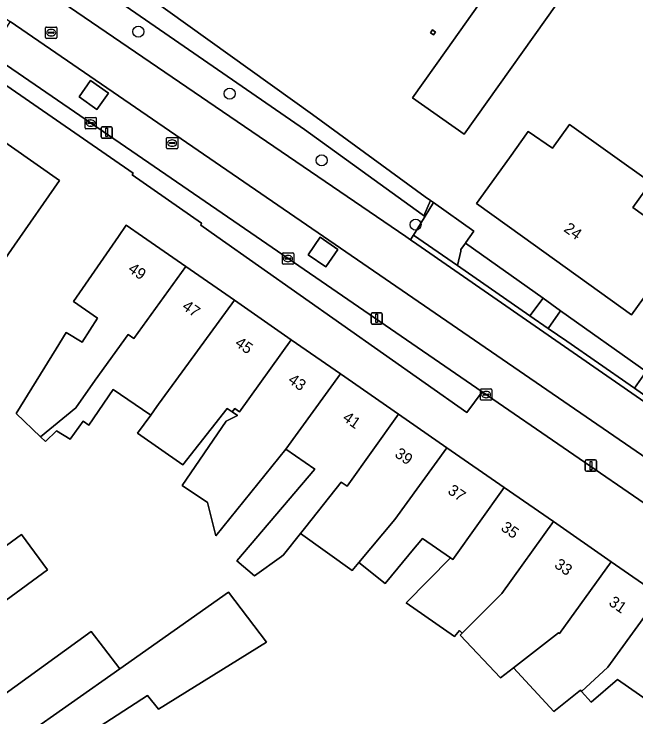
# Model space of a CAD drawing. Extents: x 163859 to 164644, y 379566 to 382155.
# Drawn here: x 164325.1 to 164380.2, y 381707.4 to 381769.7 of the extents above; entities that cross this region are included whole.
import ezdxf

# ---------------------------------------------------------------- set-up
doc = ezdxf.new("R2010")
doc.units = 0
for name, color, linetype in [('IMGEO_Boom', 7, 'Continuous'), ('IMGEO_Brandkraan', 7, 'Continuous'), ('IMGEO_Erf', 7, 'Continuous'), ('IMGEO_Groenvoorziening', 7, 'Continuous'), ('IMGEO_Haag', 7, 'Continuous'), ('IMGEO_Kolk', 7, 'Continuous'), ('IMGEO_Lichtmast', 7, 'Continuous'), ('IMGEO_Pand', 7, 'Continuous'), ('IMGEO_Pand_nummerreeks', 7, 'Continuous'), ('IMGEO_Parkeervlak_open', 7, 'Continuous'), ('IMGEO_Rijbaan_lokaal_gesloten', 7, 'Continuous'), ('IMGEO_Rijbaan_lokaal_open', 7, 'Continuous'), ('IMGEO_Rioolput', 7, 'Continuous'), ('IMGEO_Voetpad_halfverhard', 7, 'Continuous'), ('IMGEO_Voetpad_open', 7, 'Continuous'), ('IMGEO_Waterloop', 7, 'Continuous')]:
    doc.layers.add(name, color=color, linetype=linetype)

msp = doc.modelspace()

# ---------------------------------------------------------------- linework, layer by layer
at = {"layer": 'IMGEO_Boom'}
for centre in [(164336.114, 381768.169), (164344.218, 381762.677), (164352.371, 381756.76), (164360.689, 381751.063)]:
    msp.add_circle(centre, 0.489, dxfattribs=at)
at = {"layer": 'IMGEO_Brandkraan'}
for p, q in [((164338.611, 381757.863), (164338.611, 381758.715)), ((164338.686, 381758.789), (164339.538, 381758.789)), ((164339.099, 381758.569), (164339.124, 381758.569)), ((164339.612, 381758.715), (164339.612, 381757.863)), ((164338.87, 381758.283), (164338.87, 381758.295)), ((164339.308, 381758.246), (164338.91, 381758.246)), ((164338.913, 381758.332), (164339.311, 381758.332)), ((164339.122, 381758.009), (164339.097, 381758.009)), ((164339.354, 381758.295), (164339.354, 381758.283)), ((164339.538, 381757.789), (164338.686, 381757.789))]:
    msp.add_line(p, q, dxfattribs=at)
for points in [[(164338.611, 381757.863), (164338.611, 381758.715)], [(164338.686, 381758.789), (164339.538, 381758.789)], [(164339.612, 381758.715), (164339.612, 381757.863)], [(164339.538, 381757.789), (164338.686, 381757.789)]]:
    msp.add_lwpolyline(points, dxfattribs=at)
for centre, radius, start, end in [((164338.688, 381758.713), 0.0765, 91.55205, 178.44795), ((164338.688, 381758.713), 0.0765, 91.55205, 178.44795), ((164339.536, 381758.713), 0.0765, 1.55205, 88.44795), ((164339.536, 381758.713), 0.0765, 1.55205, 88.44795), ((164338.688, 381757.865), 0.0765, 181.55205, 268.44795), ((164338.688, 381757.865), 0.0765, 181.55205, 268.44795), ((164338.91, 381758.292), 0.0403, 85.87752, 175.75265), ((164338.907, 381758.282), 0.0366, 178.93798, 274.71019), ((164339.311, 381758.289), 0.043, 264.86636, 352.45326), ((164339.315, 381758.294), 0.0386, 1.73085, 96.63898), ((164339.536, 381757.865), 0.0765, 271.55205, 358.44795), ((164339.536, 381757.865), 0.0765, 271.55205, 358.44795)]:
    msp.add_arc(centre, radius, start, end, dxfattribs=at)
for centre, major_axis, ratio, start_param, end_param in [((164339.098, 381758.289), (-0.387, 0.002), 0.722429, 4.712389, 7.853982), ((164339.123, 381758.289), (-0.39, 0.002), 0.717154, 1.570796, 4.712389)]:
    msp.add_ellipse(centre, major_axis=major_axis, ratio=ratio, start_param=start_param, end_param=end_param, dxfattribs=at)
at = {"layer": 'IMGEO_Erf'}
for points in [[(164392.726, 381806.597), (164338.747, 381777.229), (164335.006, 381775.051), (164333.203, 381774.002), (164351.545, 381760.837), (164361.552, 381753.543), (164362.019, 381753.203), (164362.264, 381753.03), (164365.86, 381750.491), (164365.15, 381749.485), (164365.11, 381749.429), (164371.983, 381744.544), (164373.541, 381743.437), (164381.128, 381738.044), (164380.075, 381736.577), (164381.302, 381735.727)], [(164381.892, 381725.724), (164366.579, 381736.251), (164365.238, 381734.407), (164343.09, 381750), (164341.646, 381751.017), (164341.728, 381751.199), (164335.582, 381755.465), (164335.669, 381755.626), (164322.057, 381765.024), (164322.896, 381766.247), (164322.167, 381766.721), (164321.202, 381765.27), (164309.218, 381773.471), (164309.769, 381774.13), (164309.527, 381774.292), (164308.748, 381773.279), (164308.401, 381772.828), (164307.015, 381771.024), (164290.861, 381750), (164280.775, 381736.889), (164280.475, 381736.472), (164297.431, 381715.017), (164336.625, 381665.424)], [(164382.491, 381708.022), (164378.587, 381710.736), (164376.254, 381708.729), (164375.391, 381709.7), (164375.31, 381709.792), (164372.95, 381707.902), (164369.371, 381711.799), (164368.221, 381710.906), (164364.655, 381714.683), (164364.832, 381714.86), (164364.572, 381715.105), (164364.139, 381714.554), (164359.852, 381717.545), (164363.776, 381721.527), (164361.292, 381723.25), (164360.83, 381722.692), (164360.648, 381722.472), (164357.992, 381719.262), (164355.658, 381721.111), (164355.072, 381720.411), (164350.492, 381723.687), (164348.988, 381721.786), (164348.799, 381721.652), (164346.4, 381719.939), (164344.855, 381721.269), (164351.754, 381729.39), (164349.184, 381731.176), (164342.992, 381723.477), (164342.241, 381726.45), (164339.999, 381727.945), (164343.893, 381733.653), (164344.898, 381734.156), (164344.447, 381734.469), (164344.003, 381734.777), (164340.064, 381729.783), (164336.057, 381732.584), (164337.215, 381734.183), (164337.128, 381734.243), (164333.902, 381736.447), (164331.739, 381733.298), (164331.228, 381733.653), (164330.087, 381732.039), (164328.868, 381732.787), (164327.884, 381731.842), (164327.448, 381732.259), (164325.288, 381734.322), (164328.828, 381740.068), (164329.722, 381741.519), (164331.136, 381740.648), (164332.504, 381742.772), (164330.372, 381744.254), (164332.233, 381746.93), (164334.357, 381750), (164335.053, 381751.006), (164336.503, 381750), (164340.315, 381747.355), (164344.634, 381744.357), (164349.676, 381740.859), (164354.042, 381737.829), (164359.164, 381734.275), (164363.467, 381731.289), (164368.546, 381727.764), (164372.899, 381724.743), (164378.015, 381721.193), (164382.346, 381718.188)], [(164324.281, 381704.515), (164321.939, 381707.778), (164331.952, 381715.004), (164333.032, 381713.589), (164334.47, 381711.704), (164344.097, 381718.497), (164347.475, 381714.073), (164337.908, 381708.113), (164336.94, 381709.343), (164326.849, 381702.817)]]:
    msp.add_lwpolyline(points, dxfattribs=at)
for points in [[(164364.99, 381759.075), (164360.427, 381762.301), (164363.402, 381766.508), (164369.661, 381775.357), (164374.23, 381772.12)], [(164362.279, 381767.877), (164362.018, 381768.062), (164362.203, 381768.324), (164362.464, 381768.139)], [(164320.981, 381743.295), (164317.322, 381745.846), (164321.205, 381751.416), (164318.285, 381753.452), (164317.93, 381752.943), (164313.509, 381756.026), (164316.591, 381760.447), (164320.99, 381757.29), (164322.574, 381759.563), (164329.133, 381754.99), (164325.139, 381749.259), (164322.268, 381745.141)], [(164384.356, 381749.398), (164386.461, 381747.871), (164383.511, 381743.759), (164381.407, 381745.286), (164379.821, 381743.076), (164370.167, 381750), (164366.083, 381752.929), (164368.998, 381756.992), (164370.67, 381759.324), (164372.81, 381757.83), (164374.323, 381759.95), (164381.542, 381754.8), (164379.945, 381752.598), (164383.526, 381750)], [(164324.402, 381717.768), (164322.084, 381720.911), (164325.769, 381723.593), (164328.077, 381720.464)]]:
    msp.add_lwpolyline(points, close=True, dxfattribs=at)
at = {"layer": 'IMGEO_Groenvoorziening'}
msp.add_lwpolyline([(164324.169, 381774.363), (164359.822, 381750), (164360.25, 381749.708), (164360.489, 381750.103), (164360.511, 381750.139), (164361.118, 381751.14), (164362.264, 381753.03), (164362.019, 381753.203), (164361.428, 381751.86), (164361.269, 381751.975), (164350.837, 381759.485), (164291.421, 381800.511), (164261.825, 381821.183)], dxfattribs=at)
for points in [[(164333.471, 381762.711), (164331.878, 381763.829), (164330.863, 381762.383), (164332.456, 381761.265)], [(164352.745, 381747.339), (164353.81, 381748.857), (164352.232, 381749.958), (164351.164, 381748.396)], [(164365.11, 381749.429), (164364.703, 381748.852), (164364.689, 381748.711), (164364.415, 381747.432), (164370.817, 381742.995), (164370.827, 381742.988), (164371.983, 381744.544)], [(164373.541, 381743.437), (164372.441, 381741.869), (164374.088, 381740.727), (164379.696, 381736.84), (164380.075, 381736.577), (164381.128, 381738.044)]]:
    msp.add_lwpolyline(points, close=True, dxfattribs=at)
at = {"layer": 'IMGEO_Haag'}
msp.add_lwpolyline([(164352.745, 381747.339), (164353.81, 381748.857), (164352.232, 381749.958), (164351.164, 381748.396)], close=True, dxfattribs=at)
at = {"layer": 'IMGEO_Kolk'}
for p, q in [((164331.397, 381759.642), (164331.397, 381760.494)), ((164331.472, 381760.568), (164332.324, 381760.568)), ((164331.885, 381760.348), (164331.91, 381760.348)), ((164332.398, 381760.494), (164332.398, 381759.642)), ((164331.656, 381760.062), (164331.656, 381760.074)), ((164332.094, 381760.025), (164331.696, 381760.025)), ((164331.699, 381760.111), (164332.097, 381760.111)), ((164331.908, 381759.788), (164331.883, 381759.788)), ((164332.14, 381760.074), (164332.14, 381760.062)), ((164332.324, 381759.568), (164331.472, 381759.568)), ((164348.961, 381748.558), (164349.813, 381748.558)), ((164348.886, 381747.632), (164348.886, 381748.484)), ((164349.145, 381748.052), (164349.145, 381748.064)), ((164349.583, 381748.015), (164349.185, 381748.015)), ((164349.188, 381748.101), (164349.586, 381748.101)), ((164349.374, 381748.338), (164349.399, 381748.338)), ((164349.629, 381748.064), (164349.629, 381748.052)), ((164349.887, 381748.484), (164349.887, 381747.632)), ((164349.813, 381747.558), (164348.961, 381747.558)), ((164349.397, 381747.778), (164349.372, 381747.778)), ((164366.438, 381735.579), (164366.438, 381736.431)), ((164366.513, 381736.505), (164367.365, 381736.505)), ((164366.74, 381736.048), (164367.138, 381736.048)), ((164366.926, 381736.285), (164366.951, 381736.285)), ((164367.439, 381736.431), (164367.439, 381735.579)), ((164367.365, 381735.505), (164366.513, 381735.505)), ((164366.697, 381735.999), (164366.697, 381736.011)), ((164367.135, 381735.962), (164366.737, 381735.962)), ((164366.949, 381735.725), (164366.924, 381735.725)), ((164367.181, 381736.011), (164367.181, 381735.999))]:
    msp.add_line(p, q, dxfattribs=at)
for points in [[(164331.397, 381759.642), (164331.397, 381760.494)], [(164331.472, 381760.568), (164332.324, 381760.568)], [(164332.398, 381760.494), (164332.398, 381759.642)], [(164332.324, 381759.568), (164331.472, 381759.568)], [(164348.961, 381748.558), (164349.813, 381748.558)], [(164348.886, 381747.632), (164348.886, 381748.484)], [(164349.887, 381748.484), (164349.887, 381747.632)], [(164349.813, 381747.558), (164348.961, 381747.558)], [(164366.438, 381735.579), (164366.438, 381736.431)], [(164366.513, 381736.505), (164367.365, 381736.505)], [(164367.439, 381736.431), (164367.439, 381735.579)], [(164367.365, 381735.505), (164366.513, 381735.505)]]:
    msp.add_lwpolyline(points, dxfattribs=at)
for centre, radius, start, end in [((164331.474, 381760.492), 0.0765, 91.55205, 178.44795), ((164331.474, 381760.492), 0.0765, 91.55205, 178.44795), ((164332.322, 381760.492), 0.0765, 1.55205, 88.44795), ((164332.322, 381760.492), 0.0765, 1.55205, 88.44795), ((164331.696, 381760.071), 0.0403, 85.87752, 175.75265), ((164331.693, 381760.061), 0.0366, 178.93798, 274.71019), ((164332.097, 381760.068), 0.043, 264.86636, 352.45326), ((164332.101, 381760.073), 0.0386, 1.73085, 96.63898), ((164331.474, 381759.644), 0.0765, 181.55205, 268.44795), ((164331.474, 381759.644), 0.0765, 181.55205, 268.44795), ((164332.322, 381759.644), 0.0765, 271.55205, 358.44795), ((164332.322, 381759.644), 0.0765, 271.55205, 358.44795), ((164348.963, 381748.482), 0.0765, 91.55205, 178.44795), ((164348.963, 381748.482), 0.0765, 91.55205, 178.44795), ((164349.811, 381748.482), 0.0765, 1.55205, 88.44795), ((164349.811, 381748.482), 0.0765, 1.55205, 88.44795), ((164349.185, 381748.061), 0.0403, 85.87752, 175.75265), ((164349.182, 381748.051), 0.0366, 178.93798, 274.71019), ((164349.586, 381748.058), 0.043, 264.86636, 352.45326), ((164349.59, 381748.063), 0.0386, 1.73085, 96.63898), ((164348.963, 381747.634), 0.0765, 181.55205, 268.44795), ((164348.963, 381747.634), 0.0765, 181.55205, 268.44795), ((164349.811, 381747.634), 0.0765, 271.55205, 358.44795), ((164349.811, 381747.634), 0.0765, 271.55205, 358.44795), ((164366.515, 381736.429), 0.0765, 91.55205, 178.44795), ((164366.515, 381736.429), 0.0765, 91.55205, 178.44795), ((164366.737, 381736.008), 0.0403, 85.87752, 175.75265), ((164367.142, 381736.01), 0.0386, 1.73085, 96.63898), ((164367.363, 381736.429), 0.0765, 1.55205, 88.44795), ((164367.363, 381736.429), 0.0765, 1.55205, 88.44795), ((164366.515, 381735.581), 0.0765, 181.55205, 268.44795), ((164366.515, 381735.581), 0.0765, 181.55205, 268.44795), ((164366.734, 381735.998), 0.0366, 178.93798, 274.71019), ((164367.138, 381736.005), 0.043, 264.86636, 352.45326), ((164367.363, 381735.581), 0.0765, 271.55205, 358.44795), ((164367.363, 381735.581), 0.0765, 271.55205, 358.44795)]:
    msp.add_arc(centre, radius, start, end, dxfattribs=at)
for centre, major_axis, ratio, start_param, end_param in [((164331.884, 381760.068), (-0.387, 0.002), 0.722429, 4.712389, 7.853982), ((164331.909, 381760.068), (-0.39, 0.002), 0.717154, 1.570796, 4.712389), ((164349.373, 381748.058), (-0.387, 0.002), 0.722429, 4.712389, 7.853982), ((164349.398, 381748.058), (-0.39, 0.002), 0.717154, 1.570796, 4.712389), ((164366.925, 381736.005), (-0.387, 0.002), 0.722429, 4.712389, 7.853982), ((164366.95, 381736.005), (-0.39, 0.002), 0.717154, 1.570796, 4.712389)]:
    msp.add_ellipse(centre, major_axis=major_axis, ratio=ratio, start_param=start_param, end_param=end_param, dxfattribs=at)
at = {"layer": 'IMGEO_Lichtmast'}
for p, q in [((164332.917, 381759.742), (164333.707, 381759.742)), ((164333.707, 381759.742), (164332.917, 381759.742)), ((164332.817, 381758.842), (164332.817, 381759.642)), ((164332.817, 381759.642), (164332.817, 381758.842)), ((164333.807, 381759.642), (164333.807, 381758.842)), ((164333.807, 381758.842), (164333.807, 381759.642)), ((164333.707, 381758.742), (164332.917, 381758.742)), ((164332.917, 381758.742), (164333.707, 381758.742)), ((164356.751, 381742.357), (164356.751, 381743.157)), ((164356.751, 381743.157), (164356.751, 381742.357)), ((164356.851, 381743.257), (164357.641, 381743.257)), ((164357.641, 381743.257), (164356.851, 381743.257)), ((164357.741, 381743.157), (164357.741, 381742.357)), ((164357.741, 381742.357), (164357.741, 381743.157)), ((164357.641, 381742.257), (164356.851, 381742.257)), ((164356.851, 381742.257), (164357.641, 381742.257)), ((164375.726, 381729.309), (164375.726, 381730.109)), ((164375.726, 381730.109), (164375.726, 381729.309)), ((164375.826, 381730.209), (164376.616, 381730.209)), ((164376.616, 381730.209), (164375.826, 381730.209)), ((164376.716, 381730.109), (164376.716, 381729.309)), ((164376.716, 381729.309), (164376.716, 381730.109)), ((164376.616, 381729.209), (164375.826, 381729.209)), ((164375.826, 381729.209), (164376.616, 381729.209))]:
    msp.add_line(p, q, dxfattribs=at)
for points in [[(164333.237, 381759.617), (164333.387, 381759.617), (164333.387, 381758.867), (164333.237, 381758.867), (164333.237, 381759.617)], [(164357.171, 381743.132), (164357.321, 381743.132), (164357.321, 381742.382), (164357.171, 381742.382), (164357.171, 381743.132)], [(164376.146, 381730.084), (164376.296, 381730.084), (164376.296, 381729.334), (164376.146, 381729.334), (164376.146, 381730.084)]]:
    msp.add_lwpolyline(points, dxfattribs=at)
for centre, start, end in [((164332.917, 381759.642), 90, 180), ((164332.917, 381759.642), 90, 180), ((164333.707, 381759.642), 0, 90), ((164333.707, 381759.642), 360, 90), ((164332.917, 381758.842), 180, 270), ((164332.917, 381758.842), 180, 270), ((164333.707, 381758.842), 270, 0), ((164333.707, 381758.842), 270, 0), ((164356.851, 381743.157), 90, 180), ((164356.851, 381743.157), 90, 180), ((164357.641, 381743.157), 0, 90), ((164357.641, 381743.157), 360, 90), ((164356.851, 381742.357), 180, 270), ((164356.851, 381742.357), 180, 270), ((164357.641, 381742.357), 270, 0), ((164357.641, 381742.357), 270, 0), ((164375.826, 381730.109), 90, 180), ((164375.826, 381730.109), 90, 180), ((164376.616, 381730.109), 0, 90), ((164376.616, 381730.109), 360, 90), ((164375.826, 381729.309), 180, 270), ((164375.826, 381729.309), 180, 270), ((164376.616, 381729.309), 270, 0), ((164376.616, 381729.309), 270, 0)]:
    msp.add_arc(centre, 0.1, start, end, dxfattribs=at)
at = {"layer": 'IMGEO_Pand'}
for points in [[(164363.402, 381766.508), (164360.427, 381762.301), (164364.99, 381759.075), (164374.23, 381772.12), (164369.661, 381775.357)], [(164362.279, 381767.877), (164362.464, 381768.139), (164362.203, 381768.324), (164362.018, 381768.062)], [(164322.268, 381745.141), (164325.139, 381749.259), (164329.133, 381754.99), (164322.574, 381759.563), (164320.99, 381757.29), (164316.591, 381760.447), (164313.509, 381756.026), (164317.93, 381752.943), (164318.285, 381753.452), (164321.205, 381751.416), (164317.322, 381745.846), (164320.981, 381743.295)], [(164384.356, 381749.398), (164383.526, 381750), (164379.945, 381752.598), (164381.542, 381754.8), (164374.323, 381759.95), (164372.81, 381757.83), (164370.67, 381759.324), (164368.998, 381756.992), (164366.083, 381752.929), (164370.167, 381750), (164379.821, 381743.076), (164381.407, 381745.286), (164383.511, 381743.759), (164386.461, 381747.871)], [(164335.222, 381741.333), (164335.732, 381740.98), (164340.315, 381747.355), (164336.503, 381750), (164335.053, 381751.006), (164334.357, 381750), (164332.233, 381746.93), (164330.372, 381744.254), (164332.504, 381742.772), (164331.136, 381740.648), (164329.722, 381741.519), (164328.828, 381740.068), (164325.288, 381734.322), (164327.448, 381732.259), (164330.585, 381734.833), (164332.309, 381737.287)], [(164344.634, 381744.357), (164340.315, 381747.355), (164335.732, 381740.98), (164335.222, 381741.333), (164332.309, 381737.287), (164330.585, 381734.833), (164327.448, 381732.259), (164327.884, 381731.842), (164328.868, 381732.787), (164330.087, 381732.039), (164331.228, 381733.653), (164331.739, 381733.298), (164333.902, 381736.447), (164337.128, 381734.243), (164337.215, 381734.183), (164337.767, 381734.945), (164337.914, 381735.147), (164339.996, 381738.021)], [(164349.676, 381740.859), (164344.634, 381744.357), (164339.996, 381738.021), (164337.914, 381735.147), (164337.767, 381734.945), (164337.215, 381734.183), (164336.057, 381732.584), (164340.064, 381729.783), (164344.003, 381734.777), (164344.447, 381734.469), (164344.672, 381734.779), (164345.091, 381734.488)], [(164354.042, 381737.829), (164349.676, 381740.859), (164345.091, 381734.488), (164344.672, 381734.779), (164344.447, 381734.469), (164344.898, 381734.156), (164343.893, 381733.653), (164339.999, 381727.945), (164342.241, 381726.45), (164342.992, 381723.477), (164349.184, 381731.176)], [(164354.097, 381728.241), (164354.614, 381727.882), (164359.164, 381734.275), (164354.042, 381737.829), (164349.184, 381731.176), (164351.754, 381729.39), (164344.855, 381721.269), (164346.4, 381719.939), (164348.799, 381721.652), (164348.988, 381721.786), (164350.492, 381723.687), (164350.961, 381724.279)], [(164363.467, 381731.289), (164359.164, 381734.275), (164354.614, 381727.882), (164354.097, 381728.241), (164350.961, 381724.279), (164350.492, 381723.687), (164355.072, 381720.411), (164355.658, 381721.111), (164358.862, 381724.936)], [(164368.546, 381727.764), (164363.467, 381731.289), (164358.862, 381724.936), (164355.658, 381721.111), (164357.992, 381719.262), (164360.648, 381722.472), (164360.83, 381722.692), (164361.292, 381723.25), (164363.776, 381721.527), (164363.998, 381721.373)], [(164372.899, 381724.743), (164368.546, 381727.764), (164363.998, 381721.373), (164363.776, 381721.527), (164359.852, 381717.545), (164364.139, 381714.554), (164364.572, 381715.105), (164364.832, 381714.86), (164368.328, 381718.37)], [(164378.015, 381721.193), (164372.899, 381724.743), (164368.328, 381718.37), (164364.832, 381714.86), (164364.655, 381714.683), (164368.221, 381710.906), (164369.371, 381711.799), (164373.349, 381714.887), (164373.447, 381714.819)], [(164324.402, 381717.768), (164328.077, 381720.464), (164325.769, 381723.593), (164322.084, 381720.911)], [(164369.371, 381711.799), (164372.95, 381707.902), (164375.31, 381709.792), (164375.391, 381709.7), (164377.736, 381711.844), (164382.346, 381718.188), (164378.015, 381721.193), (164373.447, 381714.819), (164373.349, 381714.887)], [(164347.475, 381714.073), (164344.097, 381718.497), (164334.47, 381711.704), (164325.914, 381705.667), (164325.221, 381705.178), (164326.849, 381702.817), (164336.94, 381709.343), (164337.908, 381708.113)], [(164387.477, 381714.627), (164382.346, 381718.188), (164377.736, 381711.844), (164375.391, 381709.7), (164376.254, 381708.729), (164378.587, 381710.736), (164382.491, 381708.022), (164382.888, 381708.27), (164382.979, 381708.208)], [(164334.47, 381711.704), (164333.032, 381713.589), (164331.952, 381715.004), (164321.939, 381707.778), (164324.281, 381704.515), (164325.221, 381705.178), (164325.914, 381705.667)]]:
    msp.add_lwpolyline(points, close=True, dxfattribs=at)
at = {"layer": 'IMGEO_Parkeervlak_open'}
for points in [[(164352.536, 381750), (164324.768, 381769.068), (164324.32, 381768.391), (164323.62, 381767.407), (164322.896, 381766.247), (164346.556, 381750), (164366.579, 381736.251), (164381.892, 381725.724), (164406.418, 381708.86), (164407.122, 381709.878), (164407.816, 381710.901), (164408.346, 381711.663), (164383.72, 381728.586)], [(164332.456, 381761.265), (164330.863, 381762.383), (164331.878, 381763.829), (164333.471, 381762.711)], [(164352.745, 381747.339), (164351.164, 381748.396), (164352.232, 381749.958), (164353.81, 381748.857)]]:
    msp.add_lwpolyline(points, close=True, dxfattribs=at)
at = {"layer": 'IMGEO_Rijbaan_lokaal_gesloten'}
msp.add_lwpolyline([(164322.955, 381770.199), (164324.768, 381769.068), (164352.536, 381750), (164383.72, 381728.586), (164408.346, 381711.663), (164410.608, 381714.952), (164385.909, 381731.949), (164382.848, 381734.057), (164381.018, 381735.317), (164360.792, 381749.337), (164360.25, 381749.708), (164359.822, 381750), (164324.169, 381774.363)], dxfattribs=at)
at = {"layer": 'IMGEO_Rijbaan_lokaal_open'}
msp.add_lwpolyline([(164365.86, 381750.491), (164362.264, 381753.03), (164361.118, 381751.14), (164360.511, 381750.139), (164364.415, 381747.432), (164364.689, 381748.711), (164364.703, 381748.852), (164365.11, 381749.429), (164365.15, 381749.485)], close=True, dxfattribs=at)
at = {"layer": 'IMGEO_Rioolput'}
for p, q in [((164327.893, 381767.651), (164327.893, 381768.503)), ((164327.968, 381768.577), (164328.82, 381768.577)), ((164328.894, 381768.503), (164328.894, 381767.651)), ((164328.152, 381768.071), (164328.152, 381768.083)), ((164328.59, 381768.034), (164328.192, 381768.034)), ((164328.195, 381768.12), (164328.593, 381768.12)), ((164328.381, 381768.357), (164328.406, 381768.357)), ((164328.636, 381768.083), (164328.636, 381768.071)), ((164328.82, 381767.577), (164327.968, 381767.577)), ((164328.404, 381767.797), (164328.379, 381767.797))]:
    msp.add_line(p, q, dxfattribs=at)
for points in [[(164327.893, 381767.651), (164327.893, 381768.503)], [(164327.968, 381768.577), (164328.82, 381768.577)], [(164328.894, 381768.503), (164328.894, 381767.651)], [(164328.82, 381767.577), (164327.968, 381767.577)]]:
    msp.add_lwpolyline(points, dxfattribs=at)
for centre, radius, start, end in [((164327.97, 381768.501), 0.0765, 91.55205, 178.44795), ((164327.97, 381768.501), 0.0765, 91.55205, 178.44795), ((164328.818, 381768.501), 0.0765, 1.55205, 88.44795), ((164328.818, 381768.501), 0.0765, 1.55205, 88.44795), ((164328.192, 381768.08), 0.0403, 85.87752, 175.75265), ((164328.189, 381768.07), 0.0366, 178.93798, 274.71019), ((164328.593, 381768.077), 0.043, 264.86636, 352.45326), ((164328.597, 381768.082), 0.0386, 1.73085, 96.63898), ((164327.97, 381767.653), 0.0765, 181.55205, 268.44795), ((164327.97, 381767.653), 0.0765, 181.55205, 268.44795), ((164328.818, 381767.653), 0.0765, 271.55205, 358.44795), ((164328.818, 381767.653), 0.0765, 271.55205, 358.44795)]:
    msp.add_arc(centre, radius, start, end, dxfattribs=at)
for centre, major_axis, ratio, start_param, end_param in [((164328.38, 381768.077), (-0.387, 0.002), 0.722429, 4.712389, 7.853982), ((164328.405, 381768.077), (-0.39, 0.002), 0.717154, 1.570796, 4.712389)]:
    msp.add_ellipse(centre, major_axis=major_axis, ratio=ratio, start_param=start_param, end_param=end_param, dxfattribs=at)
at = {"layer": 'IMGEO_Voetpad_halfverhard'}
msp.add_lwpolyline([(164370.827, 381742.988), (164370.817, 381742.995), (164364.415, 381747.432), (164360.511, 381750.139), (164360.489, 381750.103), (164360.25, 381749.708), (164360.792, 381749.337), (164381.018, 381735.317), (164381.302, 381735.727), (164380.075, 381736.577), (164379.696, 381736.84), (164374.088, 381740.727), (164372.441, 381741.869)], close=True, dxfattribs=at)
at = {"layer": 'IMGEO_Voetpad_open'}
for points in [[(164322.896, 381766.247), (164322.057, 381765.024), (164335.669, 381755.626), (164335.582, 381755.465), (164341.728, 381751.199), (164341.646, 381751.017), (164343.09, 381750), (164365.238, 381734.407), (164366.579, 381736.251), (164346.556, 381750)], [(164373.541, 381743.437), (164371.983, 381744.544), (164370.827, 381742.988), (164372.441, 381741.869)]]:
    msp.add_lwpolyline(points, close=True, dxfattribs=at)
at = {"layer": 'IMGEO_Waterloop'}
msp.add_lwpolyline([(164293.413, 381802.563), (164264.597, 381822.915), (164263.512, 381823.639), (164244.45, 381836.352), (164223.061, 381850.617), (164221.968, 381849.023), (164261.825, 381821.183), (164291.421, 381800.511), (164350.837, 381759.485), (164361.269, 381751.975), (164361.428, 381751.86), (164362.019, 381753.203), (164361.552, 381753.543), (164351.545, 381760.837), (164333.203, 381774.002)], close=True, dxfattribs=at)

# ---------------------------------------------------------------- texts
at = {"layer": 'IMGEO_Pand_nummerreeks'}
for s, rotation, p in [('24', 324.34689, (164373.75, 381750.532)), ('49', 325.24438, (164335.135, 381746.957)), ('47', 325.24438, (164339.925, 381743.633)), ('45', 325.24438, (164344.606, 381740.385)), ('43', 325.24438, (164349.31, 381737.12)), ('41', 325.24438, (164354.147, 381733.763)), ('39', 325.24438, (164358.766, 381730.558)), ('37', 325.24438, (164363.457, 381727.303)), ('35', 325.24155, (164368.173, 381724.03)), ('33', 325.24438, (164372.908, 381720.744)), ('31', 325.24155, (164377.724, 381717.402))]:
    msp.add_text(s, height=1, rotation=rotation, dxfattribs=at).set_placement(p)

doc.saveas('drawing.dxf')
